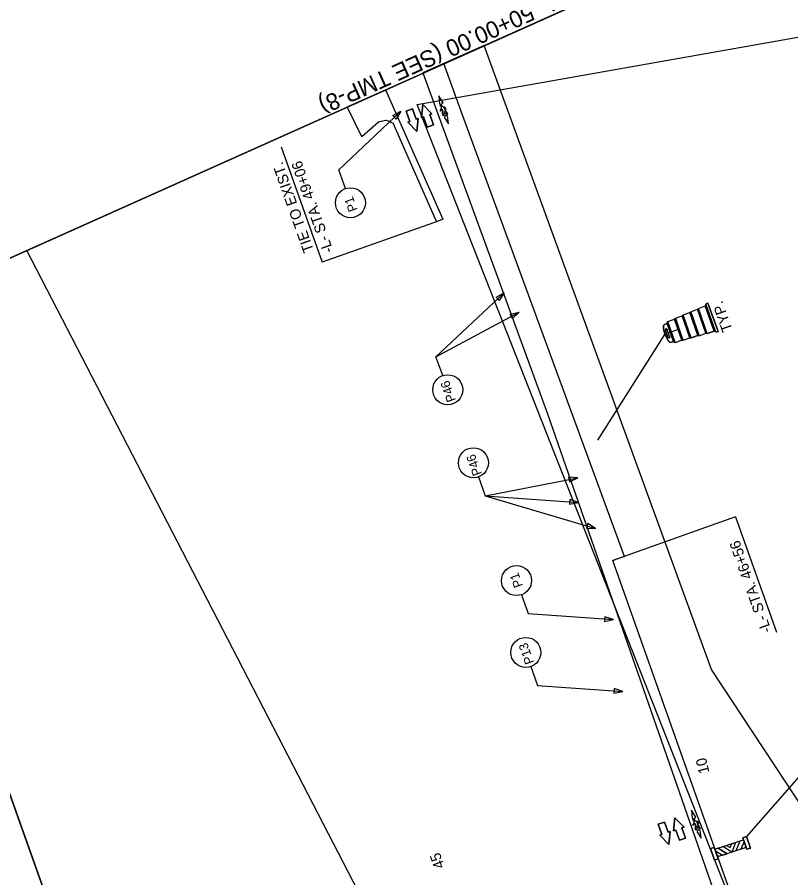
# Model space of a CAD drawing. Extents: x 1615843 to 1618439, y 899470 to 903922.
# Drawn here: x 1616107 to 1616617, y 902993 to 903560 of the extents above; entities that cross this region are included whole.
import ezdxf

# ---------------------------------------------------------------- set-up
doc = ezdxf.new("R2010")
doc.units = 0
for name, color, linetype in [('Default', 7, 'Continuous'), ('DEV DIRECTION OF TRAFFIC FLOW ARROW CELL', 7, 'Continuous'), ('DEV DRUM SECTIONAL VIEW CELL', 7, 'Continuous'), ('DEV PED BARRICDE PLAN VIEW CELL', 7, 'Continuous'), ('Matchline', 7, 'Continuous'), ('Matchline Text', 7, 'Continuous'), ('Prop DSN Text', 7, 'Continuous'), ('Prop Horizontal Alignment Tick Label', 7, 'Continuous'), ('Scratch_Level_0', 7, 'Continuous'), ('Scratch_Level_5', 7, 'Continuous'), ('Sheet Clip Boundary CELL', 7, 'Continuous')]:
    doc.layers.add(name, color=color, linetype=linetype)

msp = doc.modelspace()

# ---------------------------------------------------------------- linework, layer by layer
at = {"layer": 'Default'}
for p, q in [((1616382.9, 903336.09), (1616437.61, 903365.36)), ((1616415.25, 903244.52), (1616476.2, 903256.36)), ((1616415.25, 903244.52), (1616488, 903223.04)), ((1616655.34, 903097.86), (1616587.39, 903020.2))]:
    msp.add_line(p, q, dxfattribs=at)
for points in [[(1616323.25, 903446.78), (1616318.83, 903459.19), (1616359.81, 903497.7)], [(1616387.31, 903323.68), (1616382.9, 903336.09), (1616427.75, 903378.24)], [(1616410.83, 903256.93), (1616415.25, 903244.52), (1616476.64, 903240.14)], [(1616439.22, 903179.39), (1616443.63, 903166.97), (1616499.72, 903162.97)], [(1616445.36, 903132.09), (1616449.77, 903119.68), (1616505.86, 903115.67)]]:
    msp.add_lwpolyline(points, dxfattribs=at)
for points in [[(1616354.52, 903494.86), (1616359.81, 903497.7), (1616356.65, 903492.6)], [(1616422.46, 903375.4), (1616427.75, 903378.24), (1616424.59, 903373.14)], [(1616431.77, 903364), (1616437.61, 903365.36), (1616433.23, 903361.26)], [(1616470.81, 903253.73), (1616476.2, 903256.36), (1616470.22, 903256.78)], [(1616470.75, 903239), (1616476.64, 903240.14), (1616470.97, 903242.1)], [(1616482.01, 903223.19), (1616488, 903223.04), (1616482.89, 903226.17)], [(1616493.83, 903161.84), (1616499.72, 903162.97), (1616494.05, 903164.93)], [(1616499.97, 903114.54), (1616505.86, 903115.67), (1616500.19, 903117.64)]]:
    msp.add_lwpolyline(points, close=True, dxfattribs=at)
for centre in [(1616326.56, 903437.46), (1616390.62, 903314.35), (1616407.52, 903266.26), (1616435.91, 903188.71), (1616442.05, 903141.41)]:
    msp.add_circle(centre, 9.89, dxfattribs=at)
at = {"layer": 'DEV DIRECTION OF TRAFFIC FLOW ARROW CELL'}
for p, q in [((1616384.69, 903507.79), (1616385.22, 903502.51)), ((1616387.52, 903503.3), (1616384.69, 903507.79)), ((1616374.17, 903502.05), (1616373.32, 903493.52)), ((1616373.32, 903493.52), (1616374.17, 903502.05)), ((1616380.21, 903495.96), (1616374.17, 903502.05)), ((1616374.17, 903502.05), (1616380.21, 903495.96)), ((1616385.22, 903502.51), (1616385.68, 903502.67)), ((1616385.68, 903502.67), (1616385.83, 903502.23)), ((1616385.83, 903502.23), (1616387.2, 903502.7)), ((1616386.47, 903499.24), (1616386.39, 903499.73)), ((1616387.05, 903503.14), (1616387.52, 903503.3)), ((1616387.2, 903502.7), (1616387.05, 903503.14)), ((1616387.38, 903500.89), (1616388.81, 903500.59)), ((1616388.48, 903500.14), (1616388.07, 903500.08)), ((1616389.05, 903498.84), (1616388.48, 903500.14)), ((1616388.81, 903500.59), (1616389.38, 903498.96)), ((1616367.33, 903499.27), (1616363.23, 903497.81)), ((1616363.23, 903497.81), (1616367.33, 903499.27)), ((1616363.23, 903497.81), (1616365.64, 903491.03)), ((1616365.64, 903491.03), (1616363.23, 903497.81)), ((1616369.74, 903492.48), (1616367.33, 903499.27)), ((1616367.33, 903499.27), (1616369.74, 903492.48)), ((1616373.32, 903493.52), (1616374.72, 903494.02)), ((1616374.72, 903494.02), (1616373.32, 903493.52)), ((1616374.72, 903494.02), (1616377.12, 903487.23)), ((1616377.12, 903487.23), (1616374.72, 903494.02)), ((1616378.81, 903495.47), (1616380.21, 903495.96)), ((1616380.21, 903495.96), (1616378.81, 903495.47)), ((1616381.22, 903488.68), (1616378.81, 903495.47)), ((1616378.81, 903495.47), (1616381.22, 903488.68)), ((1616385.56, 903498.07), (1616386.47, 903499.24)), ((1616385.83, 903497.87), (1616385.56, 903498.07)), ((1616386.79, 903498.6), (1616385.83, 903497.87)), ((1616387.04, 903499.06), (1616386.79, 903498.6)), ((1616387.29, 903496.97), (1616387.51, 903498.24)), ((1616387.45, 903494.88), (1616387.29, 903496.97)), ((1616388.14, 903494.9), (1616387.45, 903494.88)), ((1616388.36, 903497.56), (1616388.06, 903496.94)), ((1616388.06, 903496.94), (1616388.14, 903494.9)), ((1616388.66, 903494.01), (1616388.2, 903493.85)), ((1616388.2, 903493.85), (1616391.03, 903489.35)), ((1616390.14, 903495.43), (1616388.36, 903497.56)), ((1616389.88, 903494.92), (1616388.51, 903494.45)), ((1616388.51, 903494.45), (1616388.66, 903494.01)), ((1616389, 903498.25), (1616390.49, 903495.91)), ((1616389.38, 903498.96), (1616389.05, 903498.84)), ((1616390.03, 903494.48), (1616389.88, 903494.92)), ((1616390.5, 903494.64), (1616390.03, 903494.48)), ((1616390.49, 903495.91), (1616390.14, 903495.43)), ((1616391.03, 903489.35), (1616390.5, 903494.64)), ((1616365.64, 903491.03), (1616364.25, 903490.53)), ((1616364.25, 903490.53), (1616365.64, 903491.03)), ((1616364.25, 903490.53), (1616370.28, 903484.45)), ((1616370.28, 903484.45), (1616364.25, 903490.53)), ((1616371.13, 903492.98), (1616369.74, 903492.48)), ((1616369.74, 903492.48), (1616371.13, 903492.98)), ((1616370.28, 903484.45), (1616371.13, 903492.98)), ((1616371.13, 903492.98), (1616370.28, 903484.45)), ((1616377.12, 903487.23), (1616381.22, 903488.68)), ((1616381.22, 903488.68), (1616377.12, 903487.23)), ((1616551.1, 903037.45), (1616551.63, 903032.17)), ((1616553.93, 903032.95), (1616551.1, 903037.45)), ((1616533.37, 903029.73), (1616529.28, 903028.27)), ((1616529.28, 903028.27), (1616533.37, 903029.73)), ((1616535.78, 903022.94), (1616533.37, 903029.73)), ((1616533.37, 903029.73), (1616535.78, 903022.94)), ((1616540.22, 903032.51), (1616539.37, 903023.98)), ((1616539.37, 903023.98), (1616540.22, 903032.51)), ((1616546.25, 903026.42), (1616540.22, 903032.51)), ((1616540.22, 903032.51), (1616546.25, 903026.42)), ((1616551.63, 903032.17), (1616552.09, 903032.33)), ((1616552.09, 903032.33), (1616552.24, 903031.88)), ((1616552.24, 903031.88), (1616553.61, 903032.35)), ((1616552.88, 903028.9), (1616552.8, 903029.39)), ((1616553.46, 903032.79), (1616553.93, 903032.95)), ((1616553.61, 903032.35), (1616553.46, 903032.79)), ((1616553.79, 903030.54), (1616555.22, 903030.24)), ((1616554.89, 903029.79), (1616554.48, 903029.73)), ((1616555.46, 903028.49), (1616554.89, 903029.79)), ((1616555.22, 903030.24), (1616555.8, 903028.61)), ((1616529.28, 903028.27), (1616531.68, 903021.49)), ((1616531.68, 903021.49), (1616529.28, 903028.27)), ((1616537.17, 903023.43), (1616535.78, 903022.94)), ((1616535.78, 903022.94), (1616537.17, 903023.43)), ((1616536.32, 903014.91), (1616537.17, 903023.43)), ((1616537.17, 903023.43), (1616536.32, 903014.91)), ((1616539.37, 903023.98), (1616540.76, 903024.47)), ((1616540.76, 903024.47), (1616539.37, 903023.98)), ((1616540.76, 903024.47), (1616543.17, 903017.69)), ((1616543.17, 903017.69), (1616540.76, 903024.47)), ((1616544.86, 903025.93), (1616546.25, 903026.42)), ((1616546.25, 903026.42), (1616544.86, 903025.93)), ((1616547.27, 903019.14), (1616544.86, 903025.93)), ((1616544.86, 903025.93), (1616547.27, 903019.14)), ((1616551.97, 903027.72), (1616552.88, 903028.9)), ((1616552.24, 903027.52), (1616551.97, 903027.72)), ((1616553.2, 903028.25), (1616552.24, 903027.52)), ((1616553.46, 903028.72), (1616553.2, 903028.25)), ((1616553.7, 903026.62), (1616553.92, 903027.89)), ((1616553.86, 903024.53), (1616553.7, 903026.62)), ((1616554.55, 903024.55), (1616553.86, 903024.53)), ((1616554.77, 903027.21), (1616554.47, 903026.59)), ((1616554.47, 903026.59), (1616554.55, 903024.55)), ((1616555.07, 903023.66), (1616554.61, 903023.5)), ((1616554.61, 903023.5), (1616557.44, 903019.01)), ((1616556.55, 903025.08), (1616554.77, 903027.21)), ((1616556.29, 903024.57), (1616554.92, 903024.1)), ((1616554.92, 903024.1), (1616555.07, 903023.66)), ((1616555.41, 903027.91), (1616556.9, 903025.56)), ((1616555.8, 903028.61), (1616555.46, 903028.49)), ((1616556.44, 903024.13), (1616556.29, 903024.57)), ((1616556.91, 903024.29), (1616556.44, 903024.13)), ((1616556.9, 903025.56), (1616556.55, 903025.08)), ((1616557.44, 903019.01), (1616556.91, 903024.29)), ((1616531.68, 903021.49), (1616530.29, 903020.99)), ((1616530.29, 903020.99), (1616531.68, 903021.49)), ((1616530.29, 903020.99), (1616536.32, 903014.91)), ((1616536.32, 903014.91), (1616530.29, 903020.99)), ((1616543.17, 903017.69), (1616547.27, 903019.14)), ((1616547.27, 903019.14), (1616543.17, 903017.69))]:
    msp.add_line(p, q, dxfattribs=at)
for centre in [(1616386.21, 903501.32), (1616552.62, 903030.98)]:
    msp.add_circle(centre, 0.555, dxfattribs=at)
for centre, radius, start, end in [((1616387.98, 903500), 1.61, 159.152, 189.5398), ((1616386.86, 903500.42), 0.42, 115.8648, 159.152), ((1616387.16, 903499.82), 1.09, 78.13, 115.8648), ((1616384.95, 903497.35), 4.15, 12.6198, 41.218), ((1616384.95, 903497.35), 2.7, 19.2722, 39.3514), ((1616554.39, 903029.66), 1.61, 159.152, 189.5398), ((1616553.28, 903030.08), 0.42, 115.8648, 159.152), ((1616553.57, 903029.47), 1.09, 78.13, 115.8648), ((1616551.36, 903027), 4.15, 12.6198, 41.218), ((1616551.36, 903027), 2.7, 19.2722, 39.3514)]:
    msp.add_arc(centre, radius, start, end, dxfattribs=at)
at = {"layer": 'DEV DRUM SECTIONAL VIEW CELL'}
for p, q in [((1616555.67, 903367.91), (1616560.1, 903369.49)), ((1616560.1, 903369.49), (1616560.72, 903370.09)), ((1616565.96, 903353), (1616560.1, 903369.49)), ((1616566.85, 903352.83), (1616560.69, 903370.18)), ((1616561.9, 903371.45), (1616561.16, 903371.18)), ((1616568.59, 903352.62), (1616561.9, 903371.45)), ((1616544.96, 903362.97), (1616545.58, 903363.57)), ((1616545.58, 903363.57), (1616550.01, 903365.15)), ((1616550.96, 903348.42), (1616545.58, 903363.57)), ((1616550.01, 903365.15), (1616550.62, 903365.74)), ((1616555.39, 903350), (1616550.01, 903365.15)), ((1616550.62, 903365.74), (1616555.05, 903367.32)), ((1616556.25, 903349.92), (1616550.62, 903365.74)), ((1616555.05, 903367.32), (1616555.67, 903367.91)), ((1616560.68, 903351.5), (1616555.05, 903367.32)), ((1616561.53, 903351.43), (1616555.67, 903367.91)), ((1616535.1, 903357.97), (1616533.72, 903357.47)), ((1616539.3, 903346.16), (1616535.1, 903357.97)), ((1616535.48, 903359.23), (1616539.91, 903360.8)), ((1616540.39, 903345.42), (1616535.48, 903359.23)), ((1616539.91, 903360.8), (1616540.53, 903361.4)), ((1616544.82, 903346.99), (1616539.91, 903360.8)), ((1616540.53, 903361.4), (1616544.96, 903362.97)), ((1616545.68, 903346.92), (1616540.53, 903361.4)), ((1616550.1, 903348.49), (1616544.96, 903362.97)), ((1616534.33, 903354.37), (1616534.26, 903354.34)), ((1616561.53, 903351.43), (1616565.96, 903353)), ((1616565.97, 903353.01), (1616566.82, 903352.93)), ((1616568.59, 903352.62), (1616567.86, 903352.36)), ((1616536.43, 903348.46), (1616536.36, 903348.44)), ((1616540.39, 903345.42), (1616544.82, 903346.99)), ((1616544.82, 903346.99), (1616545.68, 903346.92)), ((1616545.68, 903346.92), (1616550.1, 903348.49)), ((1616550.1, 903348.49), (1616550.96, 903348.42)), ((1616550.96, 903348.42), (1616555.39, 903350)), ((1616555.39, 903350), (1616556.25, 903349.92)), ((1616556.25, 903349.92), (1616560.68, 903351.5)), ((1616560.68, 903351.5), (1616561.53, 903351.43)), ((1616539.3, 903346.16), (1616537.92, 903345.66))]:
    msp.add_line(p, q, dxfattribs=at)
for points in [[(1616560.68, 903351.5), (1616555.05, 903367.32), (1616555.67, 903367.91), (1616560.1, 903369.49), (1616560.72, 903370.09), (1616560.66, 903370.27), (1616560.64, 903370.39), (1616560.65, 903370.55), (1616560.68, 903370.71), (1616560.73, 903370.81), (1616560.81, 903370.93), (1616560.92, 903371.04), (1616561.01, 903371.11), (1616561.09, 903371.16), (1616561.16, 903371.18), (1616561.9, 903371.45), (1616568.59, 903352.62), (1616567.86, 903352.36), (1616567.75, 903352.33), (1616567.62, 903352.31), (1616567.5, 903352.32), (1616567.38, 903352.34), (1616567.29, 903352.37), (1616567.16, 903352.44), (1616567.05, 903352.53), (1616566.95, 903352.64), (1616566.9, 903352.71), (1616566.85, 903352.83), (1616566.82, 903352.93), (1616565.97, 903353.01), (1616561.53, 903351.43)], [(1616550.1, 903348.49), (1616544.96, 903362.97), (1616545.58, 903363.57), (1616550.01, 903365.15), (1616550.62, 903365.74), (1616556.25, 903349.92), (1616555.39, 903350), (1616550.96, 903348.42)], [(1616540.53, 903361.4), (1616543.1, 903354.16), (1616535.72, 903351.53), (1616535.5, 903352.16), (1616535.38, 903352.6), (1616535.27, 903352.98), (1616535.2, 903353.31), (1616535.11, 903353.66), (1616535.05, 903353.96), (1616535.01, 903354.1), (1616534.94, 903354.2), (1616534.81, 903354.31), (1616534.67, 903354.37), (1616534.52, 903354.4), (1616534.4, 903354.39), (1616534.26, 903354.34), (1616534.1, 903354.26), (1616533.99, 903354.13), (1616533.93, 903354.02), (1616533.91, 903353.91), (1616533.9, 903353.82), (1616533.91, 903353.72), (1616533.96, 903353.47), (1616534.02, 903353.2), (1616534.08, 903352.94), (1616534.14, 903352.67), (1616534.24, 903352.33), (1616534.34, 903351.96), (1616534.43, 903351.68), (1616534.51, 903351.44), (1616534.61, 903351.14), (1616533.68, 903350.81), (1616533.53, 903351.25), (1616533.43, 903351.59), (1616533.29, 903352.07), (1616533.2, 903352.4), (1616533.11, 903352.77), (1616533.01, 903353.2), (1616532.92, 903353.7), (1616532.84, 903354.2), (1616532.76, 903354.78), (1616532.72, 903355.29), (1616532.68, 903355.72), (1616532.68, 903355.93), (1616532.68, 903356.12), (1616532.71, 903356.32), (1616532.76, 903356.54), (1616532.84, 903356.69), (1616532.94, 903356.88), (1616533.06, 903357.03), (1616533.21, 903357.18), (1616533.34, 903357.29), (1616533.51, 903357.39), (1616533.65, 903357.45), (1616533.72, 903357.47), (1616535.1, 903357.97), (1616535.13, 903358.28), (1616535.16, 903358.45), (1616535.22, 903358.63), (1616535.27, 903358.82), (1616535.37, 903359.04), (1616535.43, 903359.15), (1616535.48, 903359.23), (1616539.91, 903360.8)], [(1616545.68, 903346.92), (1616543.1, 903354.16), (1616535.72, 903351.53), (1616535.84, 903351.18), (1616535.96, 903350.91), (1616536.07, 903350.63), (1616536.19, 903350.34), (1616536.33, 903350.03), (1616536.49, 903349.72), (1616536.65, 903349.38), (1616536.77, 903349.15), (1616536.79, 903349.01), (1616536.78, 903348.88), (1616536.74, 903348.74), (1616536.67, 903348.64), (1616536.59, 903348.55), (1616536.5, 903348.49), (1616536.3, 903348.42), (1616536.18, 903348.41), (1616536.03, 903348.43), (1616535.9, 903348.49), (1616535.77, 903348.59), (1616535.7, 903348.7), (1616535.57, 903348.95), (1616535.39, 903349.29), (1616535.06, 903350.01), (1616534.84, 903350.53), (1616534.69, 903350.93), (1616534.61, 903351.14), (1616533.68, 903350.81), (1616533.82, 903350.43), (1616534.02, 903349.93), (1616534.23, 903349.44), (1616534.48, 903348.93), (1616534.72, 903348.44), (1616535.01, 903347.92), (1616535.37, 903347.33), (1616535.59, 903346.98), (1616535.96, 903346.44), (1616536.13, 903346.21), (1616536.25, 903346.06), (1616536.4, 903345.92), (1616536.58, 903345.8), (1616536.83, 903345.68), (1616537.05, 903345.61), (1616537.25, 903345.58), (1616537.46, 903345.58), (1616537.66, 903345.59), (1616537.92, 903345.66), (1616539.3, 903346.16), (1616539.4, 903346.04), (1616539.52, 903345.93), (1616539.7, 903345.79), (1616539.89, 903345.66), (1616540.07, 903345.56), (1616540.39, 903345.42), (1616544.82, 903346.99)]]:
    msp.add_lwpolyline(points, close=True, dxfattribs=at)
for centre, radius, start, end in [((1616561.42, 903370.45), 0.783, 109.5707, 199.5707), ((1616537.8, 903357.84), 2.71, 149.0571, 177.2647), ((1616534.24, 903356), 1.57, 109.5707, 182.6215), ((1616550.35, 903356.74), 17.69, 182.6215, 216.5199), ((1616534.45, 903353.83), 0.548, 109.5707, 190.8967), ((1616551.28, 903357.07), 17.69, 190.8967, 208.2447), ((1616534.51, 903353.85), 0.548, 11.4219, 109.5707), ((1616552.39, 903357.46), 17.69, 191.4219, 207.7194), ((1616567.59, 903353.1), 0.783, 199.5707, 289.5707), ((1616536.18, 903348.96), 0.548, 208.2447, 289.5707), ((1616536.24, 903348.98), 0.548, 289.5707, 27.7194), ((1616537.39, 903347.14), 1.57, 216.5199, 289.5707), ((1616541.31, 903347.96), 2.71, 221.8767, 250.0842)]:
    msp.add_arc(centre, radius, start, end, dxfattribs=at)
at = {"layer": 'DEV PED BARRICDE PLAN VIEW CELL'}
for p, q in [((1616581.16, 903016.68), (1616585.34, 903018.1)), ((1616583.14, 903017.37), (1616585.34, 903018.1)), ((1616584.91, 903019.37), (1616587.39, 903020.2)), ((1616587.47, 903011.79), (1616584.91, 903019.37)), ((1616585.34, 903018.1), (1616587.04, 903013.06)), ((1616587.39, 903020.2), (1616589.94, 903012.62)), ((1616563.68, 903012.21), (1616566.16, 903013.04)), ((1616566.24, 903004.62), (1616563.68, 903012.21)), ((1616566.16, 903013.04), (1616568.71, 903005.46)), ((1616566.59, 903011.77), (1616580.75, 903016.55)), ((1616568.71, 903012.49), (1616566.59, 903011.77)), ((1616587.04, 903013.06), (1616568.28, 903006.73)), ((1616568.71, 903012.49), (1616574.55, 903008.85)), ((1616574.55, 903008.85), (1616568.71, 903012.49)), ((1616577.68, 903009.9), (1616571.74, 903013.52)), ((1616580.03, 903016.32), (1616577.68, 903009.9)), ((1616580.6, 903010.89), (1616583.14, 903017.37)), ((1616580.75, 903016.55), (1616581.16, 903016.68)), ((1616586.4, 903012.84), (1616586.81, 903013.72)), ((1616587.04, 903013.06), (1616586.4, 903012.84)), ((1616586.4, 903012.84), (1616586.4, 903012.84)), ((1616586.81, 903013.72), (1616587.04, 903013.06)), ((1616589.94, 903012.62), (1616587.47, 903011.79)), ((1616568.28, 903006.73), (1616566.59, 903011.77)), ((1616566.9, 903010.82), (1616571.56, 903007.84)), ((1616567.98, 903007.63), (1616568.28, 903006.73)), ((1616568.92, 903006.94), (1616567.98, 903007.63)), ((1616567.98, 903007.63), (1616567.98, 903007.63)), ((1616568.28, 903006.73), (1616568.92, 903006.94)), ((1616571.56, 903007.84), (1616574.55, 903008.85)), ((1616568.71, 903005.46), (1616566.24, 903004.62))]:
    msp.add_line(p, q, dxfattribs=at)
for points in [[(1616585.34, 903018.1), (1616585.71, 903016.99), (1616583.56, 903011.89)], [(1616571.74, 903013.52), (1616574.24, 903014.36), (1616576.67, 903012.88), (1616577.69, 903015.53), (1616580.03, 903016.32)], [(1616566.59, 903011.77), (1616566.9, 903010.82), (1616571.56, 903007.84)], [(1616583.56, 903011.89), (1616581.6, 903011.23), (1616580.6, 903010.89)]]:
    msp.add_lwpolyline(points, dxfattribs=at)
for points in [[(1616584.91, 903019.37), (1616587.47, 903011.79), (1616589.94, 903012.62), (1616587.39, 903020.2)], [(1616563.68, 903012.21), (1616566.24, 903004.62), (1616568.71, 903005.46), (1616566.16, 903013.04)]]:
    msp.add_lwpolyline(points, close=True, dxfattribs=at)
at = {"layer": 'Matchline'}
msp.add_line((1615993.9, 903352.57), (1616672.62, 903656.48), dxfattribs=at)
at = {"layer": 'Prop DSN Text'}
for p, q in [((1616280.92, 903474.33), (1616307.96, 903398.28)), ((1616385.06, 903425.58), (1616307.96, 903398.28)), ((1616489.53, 903281.24), (1616533.68, 903350.81)), ((1616580.03, 903230.61), (1616499.35, 903201.92)), ((1616580.03, 903230.61), (1616607.01, 903154.71))]:
    msp.add_line(p, q, dxfattribs=at)
at = {"layer": 'Scratch_Level_0'}
msp.add_lwpolyline([(1615938.73, 903507.75), (1616407.69, 902188.63), (1617302.81, 902506.85), (1617008.42, 903334.93), (1616896.98, 903295.32), (1616722.42, 903786.36)], close=True, dxfattribs=at)
at = {"layer": 'Scratch_Level_5'}
for points in [[(1616347.43, 902358.15), (1615993.9, 903352.57), (1616755.41, 903693.55), (1617118.27, 903131.4), (1617302.81, 902506.85), (1616959.09, 902384.66)], [(1616705.54, 902373.67), (1616699.85, 902458.96), (1616686.62, 902573.2), (1616667.04, 902687.93), (1616638.01, 902809.43), (1616596.83, 902943.32), (1616588.98, 902949.04), (1616499.35, 903201.92), (1616504.06, 903203.6), (1616506.92, 903204.49), (1616400, 903496.37), (1616388.07, 903529.07), (1616755.41, 903693.55), (1617118.27, 903131.4), (1617302.81, 902506.85), (1616959.09, 902384.66)], [(1616699.32, 902373.4), (1616633.77, 902806.46), (1616631.94, 902813.22), (1616597.93, 902897.46), (1616599.33, 902920.4), (1616597.1, 902927.03), (1616370.6, 903502.2), (1616643.52, 903550.34), (1617118.27, 903131.4), (1617302.81, 902506.85), (1616959.09, 902384.66)], [(1616384.26, 903425.29), (1616383.3, 903425.18), (1616354.59, 903489.86), (1616353.65, 903490.07), (1616353.22, 903490.75), (1616350.1, 903491.72), (1616349.69, 903491.59), (1616349.68, 903491.59), (1616345, 903490.59), (1616334.17, 903480.97), (1616324.36, 903500.54), (1616349.56, 903511.82), (1616387.34, 903426.6)]]:
    msp.add_lwpolyline(points, close=True, dxfattribs=at)
at = {"layer": 'Sheet Clip Boundary CELL'}
for points in [[(1616920.55, 902382.99), (1616489.91, 902364.33), (1616361.78, 902925.96), (1616113.49, 903406.12), (1616903.33, 903759.78), (1617118.27, 903131.4), (1617236.29, 902693.96), (1617083.45, 902390.05)], [(1616694.55, 902373.19), (1616732.15, 902374.79), (1616717.45, 902614.43), (1616639.68, 902965.04), (1616763.33, 903001.21), (1616761.22, 903018.27), (1616752.73, 903054.64), (1616632.71, 903026.28), (1616564.32, 903130.19), (1616414.61, 903540.98), (1616374.17, 903522.92), (1616456.37, 903298.56), (1616566.89, 902980.98), (1616598.23, 902894.85), (1616630.48, 902783.84), (1616648.21, 902701.52), (1616669.68, 902592.43), (1616683.11, 902510.03), (1616690.19, 902449.56), (1616690.27, 902434.92)]]:
    msp.add_lwpolyline(points, close=True, dxfattribs=at)

# ---------------------------------------------------------------- texts
at = {"layer": 'Default'}
for s, height, rotation, p in [('P1', 6, 109.5707, (1616331.31, 903432.81)), ('TYP.', 7, 109.5708, (1616578.27, 903353.85)), ('P46', 6, 109.5707, (1616396.09, 903307.48)), ('P46', 6, 109.5706, (1616413.13, 903258.98)), ('P1', 6, 109.5706, (1616440.22, 903185.28)), ('P13', 6, 109.5706, (1616447.58, 903134.81))]:
    msp.add_text(s, height=height, rotation=rotation, dxfattribs=at).set_placement(p)
at = {"layer": 'Matchline Text'}
msp.add_text('MATCHLINE -L- STA. 50+00.00 (SEE TMP-8)', height=11, rotation=204.2818, dxfattribs=at).set_placement((1616579.23, 903629.32))
at = {"layer": 'Prop DSN Text'}
for s, p in [('TIE TO EXIST.', (1616302.57, 903406.06)), ('-L- STA. 49+06', (1616315.45, 903405.67)), ('-L- STA. 46+56', (1616603.9, 903155.68))]:
    msp.add_text(s, height=7, rotation=109.5707, dxfattribs=at).set_placement(p)
at = {"layer": 'Prop Horizontal Alignment Tick Label'}
for s, rotation, p in [('10', 103.4707, (1616563.01, 903062.44)), ('45', 109.5707, (1616388.68, 903000.38))]:
    msp.add_text(s, height=7, rotation=rotation, dxfattribs=at).set_placement(p)

doc.saveas('drawing.dxf')
